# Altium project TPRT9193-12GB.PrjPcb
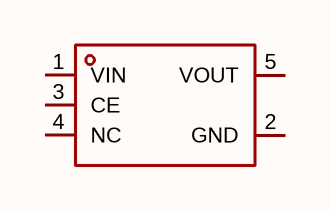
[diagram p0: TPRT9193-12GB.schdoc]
1 sheet, 1 parts. Net scope: global (net labels, ports and power ports of the same name join across sheets).

## Sheet TPRT9193-12GB.schdoc
size 127 x 101 mm

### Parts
U?  tprt9193-12gb  [SOT-23-5_L3.0-W1.6-P0.95-LS2.8-BR]  (value not drawn)

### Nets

Not connected (* = marked no-connect by the designer): U? 1(VIN) 2(GND) 3(CE) 4(NC) 5(VOUT)

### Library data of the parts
U? = tprt9193-12gb: 输出极性:正极;工作电压:6V;输出电压:1.2V;输出电流:300mA;电源纹波抑制比(PSRR):70dB@(1kHz);输出类型:固定;; Manufacturer: TECH PUBLIC(台舟); AddInBom: yes; ModelId: 72410e292833493f86746b22636ce101; ModelTransform: 110.236,116.1415,0,0,0,0,0.002,0.001,0; Output Configuration: 正极; Voltage - Supply: 6V; Output Voltage: 1.2V; Output Current: 300mA; standby current: 70uA; Noise: 50uVrms; Output Type: 固定; Number of Outputs: 1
